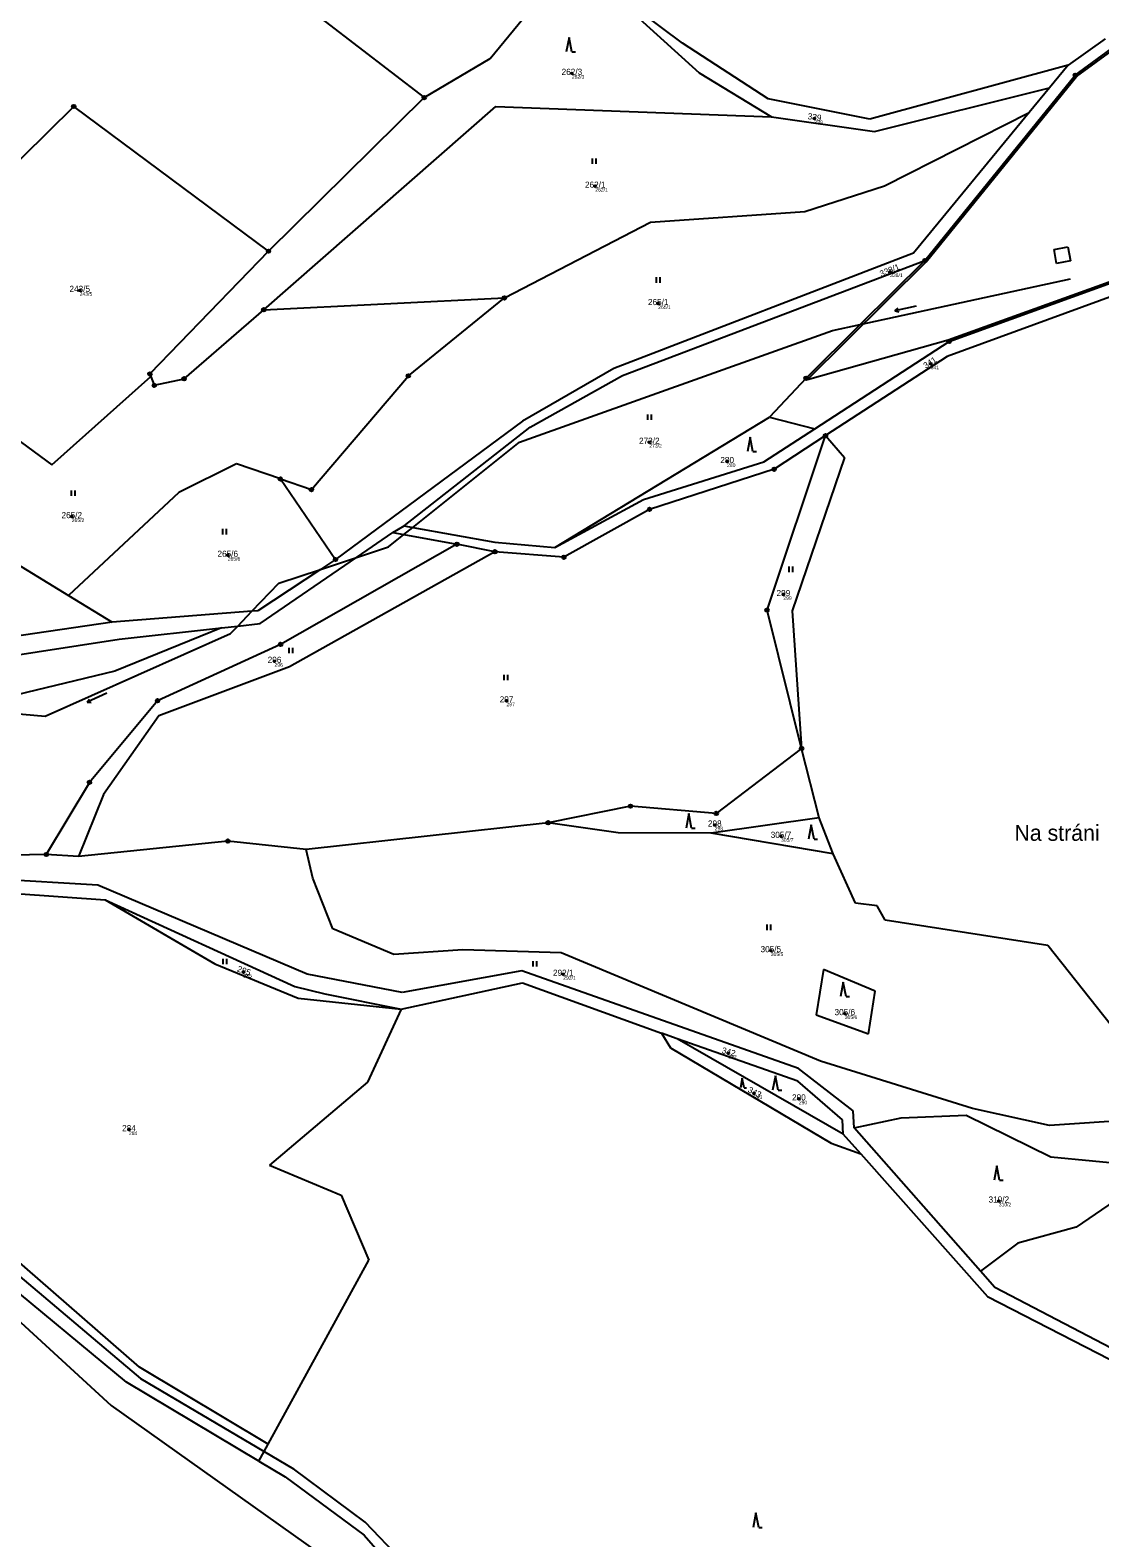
# Model space of a CAD drawing. Extents: x -867966 to -864255, y -1043242 to -1041327.
# Drawn here: x -864912.2 to -864616.5, y -1042591.8 to -1042174.8 of the extents above; entities that cross this region are included whole.
import ezdxf

# ---------------------------------------------------------------- set-up
doc = ezdxf.new("R2010")
doc.units = 0
for name, color, linetype in [('Definiční body', 7, 'Continuous'), ('Hranice parcel', 7, 'Continuous'), ('Parcelní čísla', 7, 'Continuous'), ('Pop  PČ popisy', 7, 'Continuous'), ('Vnitřní kresba', 7, 'Continuous'), ('Značky bodu BP', 7, 'Continuous'), ('Značky kultur', 7, 'Continuous')]:
    doc.layers.add(name, color=color, linetype=linetype)

msp = doc.modelspace()

# ---------------------------------------------------------------- linework, layer by layer
at = {"layer": 'Definiční body'}
for centre in [(-864762.41, -1042186.74), (-864695.38, -1042199.24), (-864755.95, -1042217.95), (-864674.43, -1042241.59), (-864898.46, -1042246.77), (-864738.54, -1042250.42), (-864663.21, -1042267.08), (-864741.01, -1042288.77), (-864719.49, -1042294.1), (-864900.66, -1042309.34), (-864857.54, -1042320.02), (-864703.95, -1042330.89), (-864844.61, -1042349.36), (-864780.48, -1042360.28), (-864722.91, -1042394.63), (-864704.61, -1042397.76), (-864707.42, -1042429.38), (-864853.2, -1042435.32), (-864764.8, -1042435.9), (-864686.97, -1042446.8), (-864719.17, -1042457.75), (-864712.07, -1042468.9), (-864699.66, -1042470.37), (-864884.85, -1042478.87), (-864644.39, -1042498.62)]:
    msp.add_circle(centre, 0.25, dxfattribs=at)
at = {"layer": 'Hranice parcel'}
for p, q in [((-864865.9, -1042145.18), (-864803.22, -1042193.45)), ((-864731.86, -1042178.41), (-864756.98, -1042159.58)), ((-864756.98, -1042159.58), (-864727.25, -1042186.57)), ((-864785.02, -1042182.68), (-864772.13, -1042166.96)), ((-864615.02, -1042177.19), (-864625.26, -1042184.48)), ((-864708.19, -1042193.82), (-864731.86, -1042178.41)), ((-864623.24, -1042187.27), (-864612.31, -1042179.25)), ((-864803.22, -1042193.45), (-864785.02, -1042182.68)), ((-864727.25, -1042186.57), (-864707.19, -1042198.8)), ((-864625.26, -1042184.48), (-864680.01, -1042199.46)), ((-864625.26, -1042184.48), (-864630.4, -1042190.74)), ((-864678.77, -1042202.79), (-864630.4, -1042190.74)), ((-864664.8, -1042238.51), (-864623.24, -1042187.27)), ((-864630.4, -1042190.74), (-864636.04, -1042197.6)), ((-864846.27, -1042235.92), (-864803.22, -1042193.45)), ((-864680.01, -1042199.46), (-864708.19, -1042193.82)), ((-864900.11, -1042195.91), (-864960.38, -1042255.07)), ((-864846.27, -1042235.92), (-864900.11, -1042195.91)), ((-864847.58, -1042252.12), (-864783.47, -1042195.92)), ((-864783.47, -1042195.92), (-864707.19, -1042198.8)), ((-864707.19, -1042198.8), (-864678.77, -1042202.79)), ((-864675.96, -1042217.86), (-864636.04, -1042197.6)), ((-864636.04, -1042197.6), (-864667.99, -1042236.47)), ((-864698, -1042224.99), (-864675.96, -1042217.86)), ((-864781.05, -1042248.86), (-864740.66, -1042227.94)), ((-864740.66, -1042227.94), (-864698, -1042224.99)), ((-864846.27, -1042235.92), (-864879.06, -1042269.88)), ((-864667.99, -1042236.47), (-864750.77, -1042268.35)), ((-864748.42, -1042270.32), (-864664.8, -1042238.51)), ((-864682.68, -1042256.22), (-864664.8, -1042238.51)), ((-864658.14, -1042260.9), (-864592.25, -1042237.07)), ((-864592.99, -1042241.02), (-864658.66, -1042265.09)), ((-864847.58, -1042252.12), (-864781.05, -1042248.86)), ((-864807.61, -1042270.4), (-864781.05, -1042248.86)), ((-864869.62, -1042271.21), (-864847.58, -1042252.12)), ((-864960.38, -1042255.07), (-864906.19, -1042295)), ((-864697.66, -1042271.07), (-864682.68, -1042256.22)), ((-864695.26, -1042285.05), (-864658.14, -1042260.9)), ((-864658.66, -1042265.09), (-864692.29, -1042286.94)), ((-864879.06, -1042269.88), (-864878.77, -1042270.62)), ((-864750.77, -1042268.35), (-864776.04, -1042282.96)), ((-864906.19, -1042295), (-864878.77, -1042270.62)), ((-864878.77, -1042270.62), (-864877.84, -1042273.02)), ((-864877.84, -1042273.02), (-864869.62, -1042271.21)), ((-864834.41, -1042301.87), (-864807.61, -1042270.4)), ((-864773.9, -1042284.6), (-864748.42, -1042270.32)), ((-864697.66, -1042271.07), (-864707.74, -1042281.79)), ((-864767.09, -1042317.9), (-864707.74, -1042281.79)), ((-864707.74, -1042281.79), (-864695.26, -1042285.05)), ((-864776.04, -1042282.96), (-864827.75, -1042321.19)), ((-864808.81, -1042311.85), (-864773.9, -1042284.6)), ((-864709.33, -1042294.2), (-864695.26, -1042285.05)), ((-864708.47, -1042335.18), (-864692.29, -1042286.94)), ((-864692.29, -1042286.94), (-864706.49, -1042296.23)), ((-864692.29, -1042286.94), (-864687.08, -1042293)), ((-864855.15, -1042294.74), (-864871.08, -1042302.7)), ((-864843, -1042298.93), (-864855.15, -1042294.74)), ((-864742.63, -1042304.63), (-864709.33, -1042294.2)), ((-864687.08, -1042293), (-864701.51, -1042335.39)), ((-864843, -1042298.93), (-864827.75, -1042321.19)), ((-864843, -1042298.93), (-864834.41, -1042301.87)), ((-864706.49, -1042296.23), (-864740.94, -1042307.33)), ((-864871.08, -1042302.7), (-864901.57, -1042331.11)), ((-864767.09, -1042317.9), (-864742.63, -1042304.63)), ((-864740.94, -1042307.33), (-864764.61, -1042320.58)), ((-864932.23, -1042312.42), (-864901.57, -1042331.11)), ((-864821.92, -1042320.63), (-864811.91, -1042313.77)), ((-864811.91, -1042313.77), (-864808.81, -1042311.85)), ((-864811.91, -1042313.77), (-864808.87, -1042314.32)), ((-864808.87, -1042314.32), (-864794.19, -1042316.97)), ((-864808.81, -1042311.85), (-864806.35, -1042312.3)), ((-864806.35, -1042312.3), (-864783.72, -1042316.39)), ((-864794.19, -1042316.97), (-864842.92, -1042344.69)), ((-864783.7, -1042319.06), (-864840.45, -1042350.91)), ((-864783.7, -1042319.06), (-864794.19, -1042316.97)), ((-864783.72, -1042316.39), (-864767.09, -1042317.9)), ((-864764.61, -1042320.58), (-864783.7, -1042319.06)), ((-864831.92, -1042323.94), (-864849.24, -1042335.39)), ((-864848.61, -1042338.93), (-864821.92, -1042320.63)), ((-864827.75, -1042321.19), (-864831.92, -1042323.94)), ((-864901.57, -1042331.11), (-864889.47, -1042338.49)), ((-864850.85, -1042335.51), (-864889.47, -1042338.49)), ((-864849.24, -1042335.39), (-864850.85, -1042335.51)), ((-864698.91, -1042373.47), (-864708.47, -1042335.18)), ((-864701.51, -1042335.39), (-864698.91, -1042373.47)), ((-864889.47, -1042338.49), (-864929.94, -1042344.44)), ((-864859.29, -1042340.1), (-864888.78, -1042352.07)), ((-864887.52, -1042343.2), (-864859.29, -1042340.1)), ((-864859.29, -1042340.1), (-864854.77, -1042339.61)), ((-864854.77, -1042339.61), (-864848.61, -1042338.93)), ((-864924.28, -1042348.92), (-864887.52, -1042343.2)), ((-864842.92, -1042344.69), (-864876.96, -1042360.26)), ((-864888.78, -1042352.07), (-864931.67, -1042362.46)), ((-864840.45, -1042350.91), (-864876.6, -1042364.46)), ((-864876.96, -1042360.26), (-864895.78, -1042382.83)), ((-864876.6, -1042364.46), (-864891.91, -1042386.23)), ((-864698.91, -1042373.47), (-864722.51, -1042391.42)), ((-864694.09, -1042392.6), (-864698.91, -1042373.47)), ((-864895.78, -1042382.83), (-864907.7, -1042402.78)), ((-864891.91, -1042386.23), (-864898.8, -1042403.35)), ((-864746.2, -1042389.41), (-864768.98, -1042394.01)), ((-864722.51, -1042391.42), (-864746.2, -1042389.41)), ((-864768.98, -1042394.01), (-864835.87, -1042401.42)), ((-864749.61, -1042396.78), (-864768.98, -1042394.01)), ((-864694.09, -1042392.6), (-864723.93, -1042396.92)), ((-864690.19, -1042402.59), (-864694.09, -1042392.6)), ((-864857.52, -1042399.07), (-864898.8, -1042403.35)), ((-864835.87, -1042401.42), (-864857.52, -1042399.07)), ((-864723.93, -1042396.92), (-864749.61, -1042396.78)), ((-864690.19, -1042402.59), (-864723.93, -1042396.92)), ((-864907.7, -1042402.78), (-864961.92, -1042403.89)), ((-864898.8, -1042403.35), (-864907.7, -1042402.78)), ((-864834.02, -1042409.33), (-864835.87, -1042401.42)), ((-864684.02, -1042416.27), (-864690.19, -1042402.59)), ((-864893.45, -1042411.22), (-864921.73, -1042409.64)), ((-864835.59, -1042435.9), (-864893.45, -1042411.22)), ((-864828.45, -1042423.33), (-864834.02, -1042409.33)), ((-864916.12, -1042413.57), (-864891.44, -1042415.32)), ((-864891.44, -1042415.32), (-864839.04, -1042439.24)), ((-864891.44, -1042415.32), (-864861.07, -1042432.99)), ((-864677.99, -1042417), (-864684.02, -1042416.27)), ((-864675.79, -1042420.95), (-864677.99, -1042417)), ((-864811.62, -1042430.41), (-864828.45, -1042423.33)), ((-864630.81, -1042427.92), (-864675.79, -1042420.95)), ((-864611.48, -1042452.36), (-864630.81, -1042427.92)), ((-864792.51, -1042429.11), (-864811.62, -1042430.41)), ((-864765.4, -1042430), (-864792.51, -1042429.11)), ((-864693.69, -1042459.94), (-864765.4, -1042430)), ((-864861.07, -1042432.99), (-864838.11, -1042442.55)), ((-864809.29, -1042440.98), (-864835.59, -1042435.9)), ((-864776.27, -1042434.91), (-864809.29, -1042440.98)), ((-864699.81, -1042461.93), (-864776.27, -1042434.91)), ((-864692.88, -1042434.63), (-864694.87, -1042447.08)), ((-864678.58, -1042440.62), (-864692.88, -1042434.63)), ((-864839.04, -1042439.24), (-864830.66, -1042441.3)), ((-864809.62, -1042445.57), (-864776.03, -1042438.27)), ((-864776.03, -1042438.27), (-864737.68, -1042452.16)), ((-864680.44, -1042452.37), (-864678.58, -1042440.62)), ((-864838.11, -1042442.55), (-864809.62, -1042445.57)), ((-864830.66, -1042441.3), (-864809.62, -1042445.57)), ((-864809.62, -1042445.57), (-864818.9, -1042465.74)), ((-864694.87, -1042447.08), (-864680.44, -1042452.37)), ((-864737.68, -1042452.16), (-864735.14, -1042456.29)), ((-864733.3, -1042453.77), (-864737.68, -1042452.16)), ((-864735.14, -1042456.29), (-864690.77, -1042482.61)), ((-864699.98, -1042465.44), (-864733.3, -1042453.77)), ((-864687.41, -1042480.09), (-864733.3, -1042453.77)), ((-864651.64, -1042473.07), (-864693.69, -1042459.94)), ((-864818.9, -1042465.74), (-864845.98, -1042488.7)), ((-864687.58, -1042476.13), (-864699.98, -1042465.44)), ((-864684.63, -1042473.64), (-864699.81, -1042461.93)), ((-864684.4, -1042478.39), (-864684.63, -1042473.64)), ((-864630.37, -1042477.71), (-864651.64, -1042473.07)), ((-864687.41, -1042480.09), (-864687.58, -1042476.13)), ((-864684.4, -1042478.39), (-864671.37, -1042475.64)), ((-864649.5, -1042517.97), (-864684.4, -1042478.39)), ((-864671.37, -1042475.64), (-864653.45, -1042474.89)), ((-864653.45, -1042474.89), (-864630.02, -1042486.37)), ((-864600.56, -1042475.78), (-864630.37, -1042477.71)), ((-864690.77, -1042482.61), (-864682.56, -1042485.55)), ((-864682.56, -1042485.55), (-864687.41, -1042480.09)), ((-864682.56, -1042485.55), (-864647.53, -1042525)), ((-864630.02, -1042486.37), (-864604.34, -1042488.84)), ((-864845.98, -1042488.7), (-864826.18, -1042496.95)), ((-864596.65, -1042487.77), (-864623.02, -1042505.84)), ((-864826.18, -1042496.95), (-864818.53, -1042515.01)), ((-864881.96, -1042544.59), (-864933.33, -1042499.81)), ((-864623.02, -1042505.84), (-864639.1, -1042510.31)), ((-864885.5, -1042548.69), (-864932.33, -1042510.02)), ((-864927.03, -1042509.34), (-864881.7, -1042547.66)), ((-864639.1, -1042510.31), (-864649.5, -1042517.97)), ((-864933.72, -1042514.9), (-864889.74, -1042555.12)), ((-864846.4, -1042565.85), (-864818.53, -1042515.01)), ((-864645.48, -1042522.51), (-864649.5, -1042517.97)), ((-864592.4, -1042550.32), (-864645.48, -1042522.51)), ((-864647.53, -1042525), (-864588.98, -1042555.08)), ((-864846.4, -1042565.85), (-864881.96, -1042544.59)), ((-864848.96, -1042570.52), (-864885.5, -1042548.69)), ((-864881.7, -1042547.66), (-864847.49, -1042567.85)), ((-864889.74, -1042555.12), (-864828.93, -1042598.41)), ((-864847.49, -1042567.85), (-864846.4, -1042565.85)), ((-864848.96, -1042570.52), (-864847.49, -1042567.85)), ((-864847.49, -1042567.85), (-864839.32, -1042572.67)), ((-864848.96, -1042570.52), (-864841.67, -1042574.89)), ((-864819.57, -1042587.46), (-864839.32, -1042572.67)), ((-864841.67, -1042574.89), (-864819.82, -1042590.98)), ((-864819.82, -1042590.98), (-864810.62, -1042601.55)), ((-864809.47, -1042597.98), (-864819.57, -1042587.46))]:
    msp.add_line(p, q, dxfattribs=at)
at = {"layer": 'Vnitřní kresba'}
for p, q in [((-864622.89, -1042187.63), (-864612.01, -1042179.65)), ((-864664.44, -1042238.86), (-864622.89, -1042187.63)), ((-864658.37, -1042260.45), (-864592.24, -1042236.54)), ((-864629.13, -1042235.48), (-864625.29, -1042234.73)), ((-864628.44, -1042239.33), (-864629.13, -1042235.48)), ((-864625.29, -1042234.73), (-864624.55, -1042238.56)), ((-864697.31, -1042271.42), (-864664.44, -1042238.86)), ((-864624.55, -1042238.56), (-864628.44, -1042239.33)), ((-864682.68, -1042256.22), (-864624.58, -1042243.58)), ((-864690.33, -1042257.89), (-864682.68, -1042256.22)), ((-864776.88, -1042288.74), (-864690.33, -1042257.89)), ((-864697.31, -1042271.42), (-864658.37, -1042260.45)), ((-864806.35, -1042312.3), (-864776.88, -1042288.74)), ((-864813.13, -1042317.72), (-864808.87, -1042314.32)), ((-864808.87, -1042314.32), (-864806.35, -1042312.3)), ((-864821.92, -1042320.63), (-864813.13, -1042317.72)), ((-864843.4, -1042327.75), (-864831.92, -1042323.94)), ((-864831.92, -1042323.94), (-864821.92, -1042320.63)), ((-864850.85, -1042335.51), (-864843.4, -1042327.75)), ((-864854.77, -1042339.61), (-864850.85, -1042335.51)), ((-864856.77, -1042341.69), (-864854.77, -1042339.61)), ((-864908.04, -1042364.55), (-864856.77, -1042341.69)), ((-864931.67, -1042362.46), (-864908.04, -1042364.55))]:
    msp.add_line(p, q, dxfattribs=at)
at = {"layer": 'Značky bodu BP'}
for centre, radius in [((-864623.24, -1042187.27), 0.5), ((-864623.24, -1042187.27), 0.0303), ((-864803.22, -1042193.45), 0.5), ((-864803.22, -1042193.45), 0.0303), ((-864900.11, -1042195.91), 0.5), ((-864900.11, -1042195.91), 0.0303), ((-864846.27, -1042235.92), 0.5), ((-864846.27, -1042235.92), 0.0303), ((-864664.8, -1042238.51), 0.5), ((-864664.8, -1042238.51), 0.0303), ((-864781.05, -1042248.86), 0.5), ((-864781.05, -1042248.86), 0.0303), ((-864847.58, -1042252.12), 0.5), ((-864847.58, -1042252.12), 0.0303), ((-864658.14, -1042260.9), 0.5), ((-864658.14, -1042260.9), 0.0303), ((-864879.06, -1042269.88), 0.5), ((-864879.06, -1042269.88), 0.0303), ((-864807.61, -1042270.4), 0.5), ((-864877.84, -1042273.02), 0.5), ((-864877.84, -1042273.02), 0.0303), ((-864869.62, -1042271.21), 0.5), ((-864869.62, -1042271.21), 0.0303), ((-864807.61, -1042270.4), 0.0303), ((-864697.66, -1042271.07), 0.5), ((-864697.66, -1042271.07), 0.0303), ((-864692.29, -1042286.94), 0.5), ((-864692.29, -1042286.94), 0.0303), ((-864843, -1042298.93), 0.5), ((-864843, -1042298.93), 0.0303), ((-864706.49, -1042296.23), 0.5), ((-864706.49, -1042296.23), 0.0303), ((-864834.41, -1042301.87), 0.5), ((-864834.41, -1042301.87), 0.0303), ((-864740.94, -1042307.33), 0.5), ((-864740.94, -1042307.33), 0.0303), ((-864794.19, -1042316.97), 0.5), ((-864794.19, -1042316.97), 0.0303), ((-864783.7, -1042319.06), 0.5), ((-864783.7, -1042319.06), 0.0303), ((-864827.75, -1042321.19), 0.5), ((-864827.75, -1042321.19), 0.0303), ((-864764.61, -1042320.58), 0.5), ((-864764.61, -1042320.58), 0.0303), ((-864708.47, -1042335.18), 0.5), ((-864708.47, -1042335.18), 0.0303), ((-864842.92, -1042344.69), 0.5), ((-864842.92, -1042344.69), 0.0303), ((-864876.96, -1042360.26), 0.5), ((-864876.96, -1042360.26), 0.0303), ((-864698.91, -1042373.47), 0.5), ((-864698.91, -1042373.47), 0.0303), ((-864895.78, -1042382.83), 0.5), ((-864895.78, -1042382.83), 0.0303), ((-864746.2, -1042389.41), 0.5), ((-864746.2, -1042389.41), 0.0303), ((-864722.51, -1042391.42), 0.5), ((-864768.98, -1042394.01), 0.5), ((-864768.98, -1042394.01), 0.0303), ((-864722.51, -1042391.42), 0.0303), ((-864857.52, -1042399.07), 0.5), ((-864857.52, -1042399.07), 0.0303), ((-864907.7, -1042402.78), 0.5), ((-864907.7, -1042402.78), 0.0303)]:
    msp.add_circle(centre, radius, dxfattribs=at)
at = {"layer": 'Značky kultur'}
for p, q in [((-864763.2, -1042176.79), (-864763.95, -1042180.79)), ((-864762.45, -1042180.79), (-864763.2, -1042176.79)), ((-864762.45, -1042180.79), (-864761.45, -1042180.79)), ((-864756.74, -1042211.77), (-864756.74, -1042210.27)), ((-864755.74, -1042211.77), (-864755.74, -1042210.27)), ((-864739.05, -1042244.64), (-864739.05, -1042243.14)), ((-864738.05, -1042244.64), (-864738.05, -1042243.14)), ((-864667.23, -1042251.13), (-864673.1, -1042252.38)), ((-864673.1, -1042252.38), (-864672.25, -1042251.69)), ((-864673.1, -1042252.38), (-864672.04, -1042252.67)), ((-864741.38, -1042282.58), (-864741.38, -1042281.08)), ((-864740.38, -1042282.58), (-864740.38, -1042281.08)), ((-864713.1, -1042287.35), (-864713.85, -1042291.35)), ((-864712.35, -1042291.35), (-864713.1, -1042287.35)), ((-864712.35, -1042291.35), (-864711.35, -1042291.35)), ((-864900.75, -1042303.57), (-864900.75, -1042302.07)), ((-864899.75, -1042303.57), (-864899.75, -1042302.07)), ((-864858.88, -1042314.25), (-864858.88, -1042312.75)), ((-864857.88, -1042314.25), (-864857.88, -1042312.75)), ((-864702.3, -1042324.67), (-864702.3, -1042323.17)), ((-864701.3, -1042324.67), (-864701.3, -1042323.17)), ((-864840.54, -1042347.13), (-864840.54, -1042345.63)), ((-864839.54, -1042347.13), (-864839.54, -1042345.63)), ((-864781.09, -1042354.6), (-864781.09, -1042353.1)), ((-864780.09, -1042354.6), (-864780.09, -1042353.1)), ((-864890.95, -1042358.2), (-864896.43, -1042360.64)), ((-864896.43, -1042360.64), (-864895.74, -1042359.78)), ((-864896.43, -1042360.64), (-864895.33, -1042360.7)), ((-864730.09, -1042391.48), (-864730.84, -1042395.48)), ((-864729.34, -1042395.48), (-864730.09, -1042391.48)), ((-864696.22, -1042394.58), (-864696.97, -1042398.58)), ((-864695.47, -1042398.58), (-864696.22, -1042394.58)), ((-864729.34, -1042395.48), (-864728.34, -1042395.48)), ((-864695.47, -1042398.58), (-864694.47, -1042398.58)), ((-864708.42, -1042423.67), (-864708.42, -1042422.17)), ((-864707.42, -1042423.67), (-864707.42, -1042422.17)), ((-864858.83, -1042433.09), (-864858.83, -1042431.59)), ((-864857.83, -1042433.09), (-864857.83, -1042431.59)), ((-864773.11, -1042433.74), (-864773.11, -1042432.24)), ((-864772.11, -1042433.74), (-864772.11, -1042432.24)), ((-864687.38, -1042438.06), (-864688.13, -1042442.06)), ((-864686.63, -1042442.06), (-864687.38, -1042438.06)), ((-864686.63, -1042442.06), (-864685.63, -1042442.06)), ((-864715.31, -1042464.6), (-864715.81, -1042467.28)), ((-864714.81, -1042467.28), (-864715.31, -1042464.6)), ((-864706.16, -1042463.96), (-864706.91, -1042467.96)), ((-864705.41, -1042467.96), (-864706.16, -1042463.96)), ((-864714.81, -1042467.28), (-864714.14, -1042467.28)), ((-864705.41, -1042467.96), (-864704.41, -1042467.96)), ((-864644.94, -1042488.84), (-864645.69, -1042492.84)), ((-864644.19, -1042492.84), (-864644.94, -1042488.84)), ((-864644.19, -1042492.84), (-864643.19, -1042492.84)), ((-864711.52, -1042584.86), (-864712.27, -1042588.86)), ((-864710.77, -1042588.86), (-864711.52, -1042584.86)), ((-864710.77, -1042588.86), (-864709.77, -1042588.86))]:
    msp.add_line(p, q, dxfattribs=at)

# ---------------------------------------------------------------- texts
at = {"layer": 'Definiční body'}
for s, p in [('262/3', (-864762.41, -1042188.23)), ('339', (-864695.38, -1042200.73)), ('262/1', (-864755.95, -1042219.44)), ('338/1', (-864674.43, -1042243.08)), ('243/5', (-864898.46, -1042248.26)), ('265/1', (-864738.54, -1042251.91)), ('341', (-864663.21, -1042268.57)), ('273/2', (-864741.01, -1042290.26)), ('280', (-864719.49, -1042295.59)), ('265/2', (-864900.66, -1042310.83)), ('265/6', (-864857.54, -1042321.51)), ('299', (-864703.95, -1042332.38)), ('296', (-864844.61, -1042350.85)), ('297', (-864780.48, -1042361.77)), ('298', (-864722.91, -1042396.12)), ('305/7', (-864704.61, -1042399.25)), ('305/5', (-864707.42, -1042430.87)), ('285', (-864853.2, -1042436.81)), ('292/1', (-864764.8, -1042437.39)), ('305/6', (-864686.97, -1042448.29)), ('342', (-864719.17, -1042459.24)), ('343', (-864712.07, -1042470.39)), ('290', (-864699.66, -1042471.86)), ('284', (-864884.85, -1042480.36)), ('310/2', (-864644.39, -1042500.11))]:
    msp.add_text(s, height=1, dxfattribs=at).set_placement(p)
at = {"layer": 'Parcelní čísla'}
for s, p in [('262/3', (-864765.25, -1042187.17)), ('262/1', (-864758.79, -1042218.38)), ('243/5', (-864901.3, -1042247.2)), ('265/1', (-864741.38, -1042250.84)), ('273/2', (-864743.85, -1042289.2)), ('280', (-864721.38, -1042294.53)), ('265/2', (-864903.5, -1042309.77)), ('265/6', (-864860.38, -1042320.45)), ('299', (-864705.84, -1042331.32)), ('296', (-864846.5, -1042349.79)), ('297', (-864782.37, -1042360.71)), ('298', (-864724.8, -1042395.06)), ('305/7', (-864707.45, -1042398.19)), ('305/5', (-864710.26, -1042429.81)), ('292/1', (-864767.64, -1042436.33)), ('305/6', (-864689.81, -1042447.22)), ('290', (-864701.55, -1042470.8)), ('284', (-864886.74, -1042479.3)), ('310/2', (-864647.23, -1042499.05))]:
    msp.add_text(s, height=1.7, dxfattribs=at).set_placement(p)
for s, rotation, p in [('339', 352, (-864697.31, -1042199.4)), ('338/1', 22, (-864676.9, -1042243.05)), ('341', 33, (-864664.56, -1042268.47)), ('285', 340, (-864855.12, -1042435.07)), ('342', 345, (-864721.11, -1042457.67)), ('343', 333, (-864713.95, -1042468.42))]:
    msp.add_text(s, height=1.7, rotation=rotation, dxfattribs=at).set_placement(p)
at = {"layer": 'Pop  PČ popisy'}
msp.add_text('Na stráni', height=4.4, dxfattribs=at).set_placement((-864640.07, -1042399))

doc.saveas('drawing.dxf')
